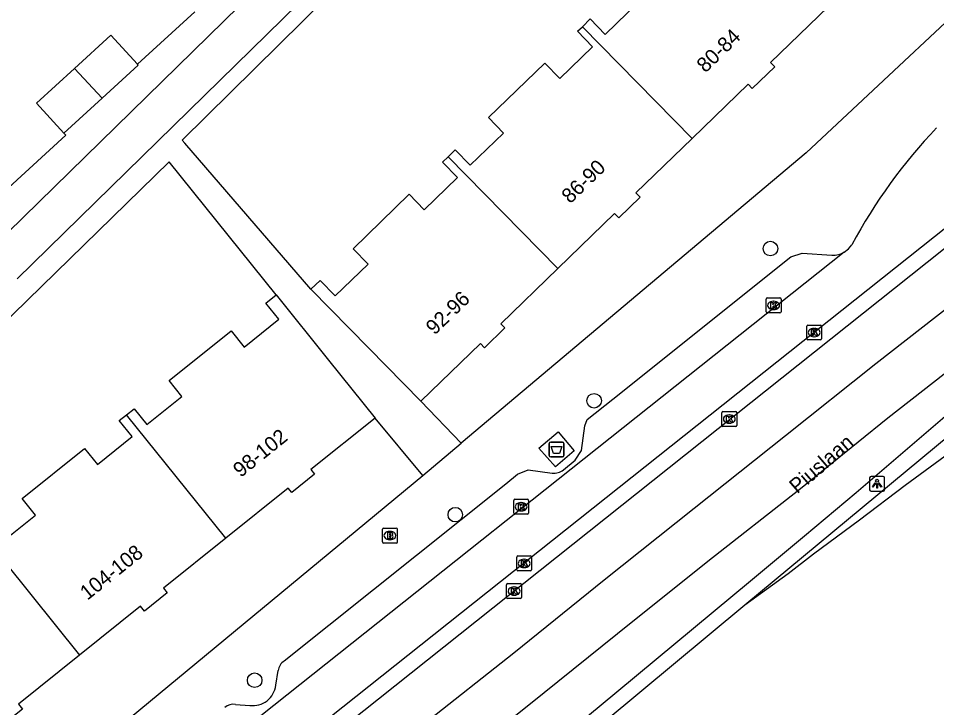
# Model space of a CAD drawing. Extents: x 161882 to 162509, y 381687 to 382379.
# Drawn here: x 162409.8 to 162471.6, y 381766.4 to 381812.8 of the extents above; entities that cross this region are included whole.
import ezdxf

# ---------------------------------------------------------------- set-up
doc = ezdxf.new("R2010")
doc.units = 0
for name, color, linetype in [('IMGEO_Afval_apart_plaats', 7, 'Continuous'), ('IMGEO_Boom', 7, 'Continuous'), ('IMGEO_Brandkraan', 7, 'Continuous'), ('IMGEO_Fietspad_gesloten', 7, 'Continuous'), ('IMGEO_Kolk', 7, 'Continuous'), ('IMGEO_Lichtpunt', 7, 'Continuous'), ('IMGEO_Openbare_ruimte_label', 7, 'Continuous'), ('IMGEO_Pand', 7, 'Continuous'), ('IMGEO_Pand_nummerreeks', 7, 'Continuous'), ('IMGEO_Rijbaan_regionaal_gesloten', 7, 'Continuous'), ('IMGEO_Voetpad_gesloten', 7, 'Continuous'), ('IMGEO_Voetpad_open', 7, 'Continuous')]:
    doc.layers.add(name, color=color, linetype=linetype)

msp = doc.modelspace()

# ---------------------------------------------------------------- linework, layer by layer
at = {"layer": 'IMGEO_Afval_apart_plaats'}
for p, q in [((162445.646, 381784.28), (162446.436, 381784.28)), ((162446.436, 381784.28), (162445.646, 381784.28)), ((162445.546, 381783.38), (162445.546, 381784.18)), ((162445.546, 381784.18), (162445.546, 381783.38)), ((162446.536, 381784.18), (162446.536, 381783.38)), ((162446.536, 381783.38), (162446.536, 381784.18)), ((162446.436, 381783.28), (162445.646, 381783.28)), ((162445.646, 381783.28), (162446.436, 381783.28))]:
    msp.add_line(p, q, dxfattribs=at)
msp.add_lwpolyline([(162445.689, 381783.994), (162446.393, 381783.994), (162446.244, 381783.524), (162445.838, 381783.524), (162445.689, 381783.994)], dxfattribs=at)
for centre, start, end in [((162445.646, 381784.18), 90, 180), ((162445.646, 381784.18), 90, 180), ((162446.436, 381784.18), 0, 90), ((162446.436, 381784.18), 360, 90), ((162445.646, 381783.38), 180, 270), ((162445.646, 381783.38), 180, 270), ((162446.436, 381783.38), 270, 0), ((162446.436, 381783.38), 270, 0)]:
    msp.add_arc(centre, 0.1, start, end, dxfattribs=at)
at = {"layer": 'IMGEO_Boom'}
for centre in [(162460.421, 381797.298), (162448.567, 381787.061), (162439.23, 381779.399), (162425.739, 381768.261)]:
    msp.add_circle(centre, 0.489, dxfattribs=at)
at = {"layer": 'IMGEO_Brandkraan'}
for p, q in [((162434.332, 381777.567), (162434.332, 381778.419)), ((162434.407, 381778.493), (162435.259, 381778.493)), ((162434.82, 381778.273), (162434.845, 381778.273)), ((162435.333, 381778.419), (162435.333, 381777.567)), ((162435.259, 381777.493), (162434.407, 381777.493)), ((162434.843, 381777.713), (162434.818, 381777.713))]:
    msp.add_line(p, q, dxfattribs=at)
for points in [[(162434.332, 381777.567), (162434.332, 381778.419)], [(162434.407, 381778.493), (162435.259, 381778.493)], [(162434.68, 381778.193), (162434.68, 381777.793), (162434.893, 381777.793)], [(162434.911, 381778.193), (162434.68, 381778.193)], [(162434.859, 381778.112), (162434.805, 381778.112), (162434.805, 381778.036)], [(162434.805, 381778.036), (162434.858, 381778.036)], [(162435.333, 381778.419), (162435.333, 381777.567)], [(162435.259, 381777.493), (162434.407, 381777.493)], [(162434.867, 381777.96), (162434.805, 381777.96), (162434.805, 381777.879)], [(162434.805, 381777.879), (162434.867, 381777.879)]]:
    msp.add_lwpolyline(points, dxfattribs=at)
for centre, radius, start, end in [((162434.409, 381778.417), 0.0765, 91.55205, 178.44795), ((162434.409, 381778.417), 0.0765, 91.55205, 178.44795), ((162434.86, 381778.074), 0.0379, 267.82845, 90.93552), ((162434.915, 381778.048), 0.145, 59.4692, 91.53667), ((162434.94, 381778.095), 0.0922, 285.51372, 58.15012), ((162435.257, 381778.417), 0.0765, 1.55205, 88.44795), ((162435.257, 381778.417), 0.0765, 1.55205, 88.44795), ((162434.409, 381777.569), 0.0765, 181.55205, 268.44795), ((162434.409, 381777.569), 0.0765, 181.55205, 268.44795), ((162434.868, 381777.919), 0.0404, 269.87594, 90.50774), ((162434.899, 381778.044), 0.251, 268.66757, 293.53466), ((162434.945, 381777.903), 0.105, 301.31148, 78.98903), ((162435.257, 381777.569), 0.0765, 271.55205, 358.44795), ((162435.257, 381777.569), 0.0765, 271.55205, 358.44795)]:
    msp.add_arc(centre, radius, start, end, dxfattribs=at)
for centre, major_axis, ratio, start_param, end_param in [((162434.819, 381777.993), (-0.387, 0.002), 0.722429, 4.712389, 7.853982), ((162434.844, 381777.993), (-0.39, 0.002), 0.717154, 1.570796, 4.712389)]:
    msp.add_ellipse(centre, major_axis=major_axis, ratio=ratio, start_param=start_param, end_param=end_param, dxfattribs=at)
at = {"layer": 'IMGEO_Fietspad_gesloten'}
for points in [[(162472.336, 381798.789), (162413.971, 381752.357), (162396.799, 381738.137)], [(162465.384, 381797.056), (162465.667, 381797.275), (162465.9, 381797.559)], [(162465.384, 381797.056), (162418.283, 381759.605), (162412.351, 381754.828), (162394.327, 381740.001), (162393.522, 381739.663)]]:
    msp.add_lwpolyline(points, dxfattribs=at)
msp.add_arc((162497.514, 381780.636), 35.859, 136.27808, 151.83984, dxfattribs=at)
at = {"layer": 'IMGEO_Kolk'}
for p, q in [((162460.133, 381793.05), (162460.133, 381793.902)), ((162460.208, 381793.976), (162461.06, 381793.976)), ((162460.621, 381793.756), (162460.646, 381793.756)), ((162461.134, 381793.902), (162461.134, 381793.05)), ((162461.06, 381792.976), (162460.208, 381792.976)), ((162460.644, 381793.196), (162460.619, 381793.196)), ((162462.862, 381791.224), (162462.862, 381792.076)), ((162462.937, 381792.15), (162463.789, 381792.15)), ((162463.35, 381791.93), (162463.375, 381791.93)), ((162463.863, 381792.076), (162463.863, 381791.224)), ((162463.789, 381791.15), (162462.937, 381791.15)), ((162463.373, 381791.37), (162463.348, 381791.37)), ((162457.158, 381785.406), (162457.158, 381786.258)), ((162457.233, 381786.332), (162458.085, 381786.332)), ((162457.646, 381786.112), (162457.671, 381786.112)), ((162458.159, 381786.258), (162458.159, 381785.406)), ((162457.669, 381785.552), (162457.644, 381785.552)), ((162458.085, 381785.332), (162457.233, 381785.332)), ((162443.157, 381779.505), (162443.157, 381780.357)), ((162443.232, 381780.431), (162444.084, 381780.431)), ((162443.645, 381780.211), (162443.67, 381780.211)), ((162444.158, 381780.357), (162444.158, 381779.505)), ((162444.084, 381779.431), (162443.232, 381779.431)), ((162443.668, 381779.651), (162443.643, 381779.651)), ((162443.362, 381775.693), (162443.362, 381776.545)), ((162443.437, 381776.619), (162444.289, 381776.619)), ((162443.85, 381776.399), (162443.875, 381776.399)), ((162444.363, 381776.545), (162444.363, 381775.693)), ((162444.289, 381775.619), (162443.437, 381775.619)), ((162443.873, 381775.839), (162443.848, 381775.839)), ((162442.685, 381773.835), (162442.685, 381774.687)), ((162442.76, 381774.761), (162443.612, 381774.761)), ((162443.173, 381774.541), (162443.198, 381774.541)), ((162443.686, 381774.687), (162443.686, 381773.835)), ((162443.612, 381773.761), (162442.76, 381773.761)), ((162443.196, 381773.981), (162443.171, 381773.981))]:
    msp.add_line(p, q, dxfattribs=at)
for points in [[(162460.133, 381793.05), (162460.133, 381793.902)], [(162460.208, 381793.976), (162461.06, 381793.976)], [(162460.454, 381793.676), (162460.577, 381793.676), (162460.577, 381793.525), (162460.707, 381793.676), (162460.871, 381793.676), (162460.725, 381793.525), (162460.878, 381793.276), (162460.726, 381793.276), (162460.641, 381793.44), (162460.577, 381793.373), (162460.577, 381793.276), (162460.454, 381793.276), (162460.454, 381793.676)], [(162461.134, 381793.902), (162461.134, 381793.05)], [(162461.06, 381792.976), (162460.208, 381792.976)], [(162462.862, 381791.224), (162462.862, 381792.076)], [(162462.937, 381792.15), (162463.789, 381792.15)], [(162463.183, 381791.85), (162463.306, 381791.85), (162463.306, 381791.699), (162463.436, 381791.85), (162463.6, 381791.85), (162463.454, 381791.699), (162463.607, 381791.45), (162463.455, 381791.45), (162463.37, 381791.614), (162463.306, 381791.547), (162463.306, 381791.45), (162463.183, 381791.45), (162463.183, 381791.85)], [(162463.863, 381792.076), (162463.863, 381791.224)], [(162463.789, 381791.15), (162462.937, 381791.15)], [(162457.158, 381785.406), (162457.158, 381786.258)], [(162457.233, 381786.332), (162458.085, 381786.332)], [(162458.159, 381786.258), (162458.159, 381785.406)], [(162457.479, 381786.032), (162457.602, 381786.032), (162457.602, 381785.881), (162457.732, 381786.032), (162457.896, 381786.032), (162457.75, 381785.881), (162457.903, 381785.632), (162457.751, 381785.632), (162457.666, 381785.796), (162457.602, 381785.729), (162457.602, 381785.632), (162457.479, 381785.632), (162457.479, 381786.032)], [(162458.085, 381785.332), (162457.233, 381785.332)], [(162443.157, 381779.505), (162443.157, 381780.357)], [(162443.232, 381780.431), (162444.084, 381780.431)], [(162443.478, 381780.131), (162443.601, 381780.131), (162443.601, 381779.98), (162443.731, 381780.131), (162443.895, 381780.131), (162443.749, 381779.98), (162443.902, 381779.731), (162443.75, 381779.731), (162443.665, 381779.895), (162443.601, 381779.828), (162443.601, 381779.731), (162443.478, 381779.731), (162443.478, 381780.131)], [(162444.158, 381780.357), (162444.158, 381779.505)], [(162444.084, 381779.431), (162443.232, 381779.431)], [(162443.362, 381775.693), (162443.362, 381776.545)], [(162443.437, 381776.619), (162444.289, 381776.619)], [(162443.683, 381776.319), (162443.806, 381776.319), (162443.806, 381776.168), (162443.936, 381776.319), (162444.1, 381776.319), (162443.954, 381776.168), (162444.107, 381775.919), (162443.955, 381775.919), (162443.87, 381776.083), (162443.806, 381776.016), (162443.806, 381775.919), (162443.683, 381775.919), (162443.683, 381776.319)], [(162444.363, 381776.545), (162444.363, 381775.693)], [(162444.289, 381775.619), (162443.437, 381775.619)], [(162442.685, 381773.835), (162442.685, 381774.687)], [(162442.76, 381774.761), (162443.612, 381774.761)], [(162443.006, 381774.461), (162443.129, 381774.461), (162443.129, 381774.31), (162443.259, 381774.461), (162443.423, 381774.461), (162443.277, 381774.31), (162443.43, 381774.061), (162443.278, 381774.061), (162443.193, 381774.225), (162443.129, 381774.158), (162443.129, 381774.061), (162443.006, 381774.061), (162443.006, 381774.461)], [(162443.686, 381774.687), (162443.686, 381773.835)], [(162443.612, 381773.761), (162442.76, 381773.761)]]:
    msp.add_lwpolyline(points, dxfattribs=at)
for centre, start, end in [((162460.21, 381793.9), 91.55205, 178.44795), ((162460.21, 381793.9), 91.55205, 178.44795), ((162461.058, 381793.9), 1.55205, 88.44795), ((162461.058, 381793.9), 1.55205, 88.44795), ((162460.21, 381793.052), 181.55205, 268.44795), ((162460.21, 381793.052), 181.55205, 268.44795), ((162461.058, 381793.052), 271.55205, 358.44795), ((162461.058, 381793.052), 271.55205, 358.44795), ((162462.939, 381792.074), 91.55205, 178.44795), ((162462.939, 381792.074), 91.55205, 178.44795), ((162463.787, 381792.074), 1.55205, 88.44795), ((162463.787, 381792.074), 1.55205, 88.44795), ((162462.939, 381791.226), 181.55205, 268.44795), ((162462.939, 381791.226), 181.55205, 268.44795), ((162463.787, 381791.226), 271.55205, 358.44795), ((162463.787, 381791.226), 271.55205, 358.44795), ((162457.235, 381786.256), 91.55205, 178.44795), ((162457.235, 381786.256), 91.55205, 178.44795), ((162458.083, 381786.256), 1.55205, 88.44795), ((162458.083, 381786.256), 1.55205, 88.44795), ((162457.235, 381785.408), 181.55205, 268.44795), ((162457.235, 381785.408), 181.55205, 268.44795), ((162458.083, 381785.408), 271.55205, 358.44795), ((162458.083, 381785.408), 271.55205, 358.44795), ((162443.234, 381780.355), 91.55205, 178.44795), ((162443.234, 381780.355), 91.55205, 178.44795), ((162444.082, 381780.355), 1.55205, 88.44795), ((162444.082, 381780.355), 1.55205, 88.44795), ((162443.234, 381779.507), 181.55205, 268.44795), ((162443.234, 381779.507), 181.55205, 268.44795), ((162444.082, 381779.507), 271.55205, 358.44795), ((162444.082, 381779.507), 271.55205, 358.44795), ((162443.439, 381776.543), 91.55205, 178.44795), ((162443.439, 381776.543), 91.55205, 178.44795), ((162444.287, 381776.543), 1.55205, 88.44795), ((162444.287, 381776.543), 1.55205, 88.44795), ((162443.439, 381775.695), 181.55205, 268.44795), ((162443.439, 381775.695), 181.55205, 268.44795), ((162444.287, 381775.695), 271.55205, 358.44795), ((162444.287, 381775.695), 271.55205, 358.44795), ((162442.762, 381774.685), 91.55205, 178.44795), ((162442.762, 381774.685), 91.55205, 178.44795), ((162443.61, 381774.685), 1.55205, 88.44795), ((162443.61, 381774.685), 1.55205, 88.44795), ((162442.762, 381773.837), 181.55205, 268.44795), ((162442.762, 381773.837), 181.55205, 268.44795), ((162443.61, 381773.837), 271.55205, 358.44795), ((162443.61, 381773.837), 271.55205, 358.44795)]:
    msp.add_arc(centre, 0.0765, start, end, dxfattribs=at)
for centre, major_axis, ratio, start_param, end_param in [((162460.62, 381793.476), (-0.387, 0.002), 0.722429, 4.712389, 7.853982), ((162460.645, 381793.476), (-0.39, 0.002), 0.717154, 1.570796, 4.712389), ((162463.349, 381791.65), (-0.387, 0.002), 0.722429, 4.712389, 7.853982), ((162463.374, 381791.65), (-0.39, 0.002), 0.717154, 1.570796, 4.712389), ((162457.645, 381785.832), (-0.387, 0.002), 0.722429, 4.712389, 7.853982), ((162457.67, 381785.832), (-0.39, 0.002), 0.717154, 1.570796, 4.712389), ((162443.644, 381779.931), (-0.387, 0.002), 0.722429, 4.712389, 7.853982), ((162443.669, 381779.931), (-0.39, 0.002), 0.717154, 1.570796, 4.712389), ((162443.849, 381776.119), (-0.387, 0.002), 0.722429, 4.712389, 7.853982), ((162443.874, 381776.119), (-0.39, 0.002), 0.717154, 1.570796, 4.712389), ((162443.172, 381774.261), (-0.387, 0.002), 0.722429, 4.712389, 7.853982), ((162443.197, 381774.261), (-0.39, 0.002), 0.717154, 1.570796, 4.712389)]:
    msp.add_ellipse(centre, major_axis=major_axis, ratio=ratio, start_param=start_param, end_param=end_param, dxfattribs=at)
at = {"layer": 'IMGEO_Lichtpunt'}
for p, q in [((162467.093, 381781.879), (162467.093, 381781.072)), ((162467.093, 381781.879), (162467.093, 381781.072)), ((162467.995, 381781.974), (162467.187, 381781.974)), ((162467.995, 381781.974), (162467.187, 381781.974)), ((162468.089, 381781.072), (162468.089, 381781.879)), ((162468.089, 381781.072), (162468.089, 381781.879)), ((162467.187, 381780.978), (162467.995, 381780.978)), ((162467.187, 381780.978), (162467.995, 381780.978))]:
    msp.add_line(p, q, dxfattribs=at)
for points in [[(162467.467, 381781.543), (162467.506, 381781.515), (162467.318, 381781.253), (162467.28, 381781.28), (162467.467, 381781.543)], [(162467.569, 381781.495), (162467.616, 381781.495), (162467.616, 381781.173), (162467.569, 381781.173), (162467.569, 381781.495)], [(162467.679, 381781.515), (162467.717, 381781.542), (162467.904, 381781.28), (162467.865, 381781.252), (162467.679, 381781.515)]]:
    msp.add_lwpolyline(points, dxfattribs=at)
msp.add_circle((162467.592, 381781.677), 0.0994, dxfattribs=at)
for centre, start, end in [((162467.187, 381781.879), 90, 180), ((162467.187, 381781.879), 90, 180), ((162467.995, 381781.879), 0, 90), ((162467.995, 381781.879), 0, 90), ((162467.187, 381781.072), 180, 270), ((162467.187, 381781.072), 180, 270), ((162467.995, 381781.072), 270, 0), ((162467.995, 381781.072), 270, 360)]:
    msp.add_arc(centre, 0.0946, start, end, dxfattribs=at)
at = {"layer": 'IMGEO_Pand'}
for points in [[(162456.915, 381821.079), (162456.549, 381820.724), (162457.558, 381819.683), (162455.331, 381817.526), (162454.322, 381818.567), (162450.544, 381814.907), (162451.553, 381813.866), (162449.319, 381811.703), (162448.31, 381812.744), (162447.776, 381812.227)], [(162408.087, 381797.371), (162426.783, 381815.673)], [(162428.663, 381813.756), (162409.777, 381795.269)], [(162455.154, 381804.701), (162458.924, 381808.352), (162459.203, 381808.065), (162460.711, 381809.526), (162460.432, 381809.813), (162464.294, 381813.553)], [(162438.742, 381803.476), (162439.224, 381803.942), (162440.233, 381802.901), (162442.474, 381805.072), (162441.465, 381806.113), (162445.243, 381809.773), (162446.252, 381808.732), (162448.464, 381810.875), (162447.455, 381811.916), (162447.776, 381812.227)], [(162447.776, 381812.227), (162455.154, 381804.701)], [(162413.626, 381809.42), (162416.068, 381811.651), (162417.855, 381809.694)], [(162415.495, 381807.419), (162417.915, 381809.629), (162417.855, 381809.694)], [(162412.909, 381805.058), (162411.063, 381807.08), (162413.626, 381809.42)], [(162413.626, 381809.42), (162415.495, 381807.419)], [(162415.495, 381807.419), (162412.909, 381805.058)], [(162455.154, 381804.701), (162451.381, 381801.048), (162451.66, 381800.761), (162450.223, 381799.369), (162449.944, 381799.656), (162446.119, 381795.952)], [(162438.742, 381803.476), (162438.369, 381803.114), (162439.378, 381802.073), (162437.144, 381799.91), (162436.135, 381800.951), (162432.357, 381797.291), (162433.366, 381796.25), (162431.161, 381794.114), (162430.152, 381795.155), (162429.518, 381794.561)], [(162446.119, 381795.952), (162438.742, 381803.476)], [(162436.906, 381787.029), (162440.915, 381790.911), (162441.194, 381790.624), (162442.573, 381791.96), (162442.294, 381792.247), (162446.119, 381795.952)], [(162417.13, 381786.119), (162417.637, 381786.526), (162418.49, 381785.464), (162420.842, 381787.353), (162419.989, 381788.416), (162424.149, 381791.757), (162425.029, 381790.66), (162427.372, 381792.541), (162426.496, 381793.632), (162427.183, 381794.183)], [(162427.183, 381794.183), (162430.705, 381789.797), (162433.836, 381785.898)], [(162436.906, 381787.029), (162433.414, 381790.589), (162429.518, 381794.561)], [(162407.314, 381778.223), (162407.768, 381778.588), (162408.653, 381777.486), (162411.003, 381779.373), (162410.105, 381780.491), (162414.302, 381783.861), (162415.174, 381782.775), (162417.505, 381784.647), (162416.639, 381785.725), (162417.13, 381786.119)], [(162423.796, 381777.824), (162417.13, 381786.119)], [(162433.836, 381785.898), (162429.524, 381782.435), (162429.773, 381782.125), (162428.235, 381780.891), (162427.992, 381781.193), (162423.796, 381777.824)], [(162407.314, 381778.223), (162413.962, 381769.95)], [(162423.796, 381777.824), (162419.601, 381774.456), (162419.852, 381774.144), (162418.326, 381772.919), (162418.065, 381773.244), (162413.962, 381769.95)], [(162413.962, 381769.95), (162409.859, 381766.656), (162410.127, 381766.323), (162408.569, 381765.072), (162408.327, 381765.372), (162404.147, 381762.016)]]:
    msp.add_lwpolyline(points, dxfattribs=at)
at = {"layer": 'IMGEO_Rijbaan_regionaal_gesloten'}
for points in [[(162354.918, 381703.865), (162355.932, 381704.593), (162374.687, 381717.125), (162383.304, 381723.196), (162388.283, 381726.848), (162394.39, 381731.453), (162400.577, 381736.34), (162406.68, 381741.16), (162412.783, 381745.979), (162418.885, 381750.799), (162424.953, 381755.663), (162430.995, 381760.424), (162437.093, 381765.307), (162443.174, 381770.102), (162449.253, 381775.014), (162455.293, 381779.828), (162461.432, 381784.719), (162467.508, 381789.56), (162473.626, 381794.349), (162479.733, 381799.057), (162485.928, 381803.772), (162492.011, 381808.462), (162495.338, 381811.162)], [(162497.319, 381808.357), (162492.901, 381805.153), (162480.582, 381795.502), (162474.449, 381790.697), (162468.315, 381785.892), (162462.329, 381781.05), (162456.203, 381776.256), (162450.144, 381771.379), (162444.176, 381766.576), (162438.061, 381761.719), (162431.945, 381756.862), (162428.87, 381754.42), (162422.805, 381749.603), (162416.695, 381744.75), (162410.545, 381739.948), (162404.375, 381735.051)], [(162497.319, 381808.357), (162484.786, 381797.114), (162471.985, 381785.848), (162466.19, 381780.862), (162462.706, 381777.955), (162459.087, 381774.927), (162448.913, 381766.462), (162439.29, 381758.51), (162435.039, 381754.997), (162428.916, 381750), (162421.805, 381744.196)], [(162502.913, 381804.071), (162494.7, 381798.828), (162493.976, 381798.359), (162490.981, 381796.418), (162487.82, 381794.369), (162484.689, 381792.273), (162481.612, 381790.099), (162478.605, 381787.975), (162475.539, 381785.809), (162472.516, 381783.584), (162469.493, 381781.359), (162466.423, 381779.021), (162463.311, 381776.74), (162461.613, 381775.429), (162458.703, 381773.301)], [(162397.154, 381737.782), (162428.678, 381762.735), (162473.156, 381798.141)], [(162480.401, 381791.319), (162458.703, 381773.301)], [(162458.703, 381773.301), (162449.246, 381765.447), (162448.728, 381765.02), (162430.504, 381750), (162395.982, 381721.548)]]:
    msp.add_lwpolyline(points, dxfattribs=at)
at = {"layer": 'IMGEO_Voetpad_gesloten'}
msp.add_lwpolyline([(162446.154, 381784.966), (162447.229, 381783.689), (162445.965, 381782.625), (162444.852, 381783.87), (162446.154, 381784.966)], dxfattribs=at)
at = {"layer": 'IMGEO_Voetpad_open'}
for points in [[(162429.518, 381794.561), (162421.052, 381804.384), (162420.873, 381804.592), (162456.614, 381839.875)], [(162478.012, 381817.966), (162477.732, 381817.717), (162462.828, 381803.734), (162439.634, 381784.212)], [(162417.855, 381809.694), (162421.709, 381813.214)], [(162409.204, 381801.418), (162413.037, 381804.918), (162412.909, 381805.058)], [(162427.183, 381794.183), (162419.997, 381803.132), (162406.611, 381790.087), (162388.399, 381772.337), (162385.299, 381769.316), (162384.304, 381770.332)], [(162446.507, 381782.417), (162447.288, 381783.074), (162447.713, 381783.712), (162447.942, 381785.382), (162448.089, 381785.805), (162449.816, 381787.175), (162461.805, 381796.747), (162462.558, 381796.999), (162464.562, 381796.862)], [(162439.634, 381784.212), (162436.906, 381787.029)], [(162437.038, 381782.026), (162433.836, 381785.898)], [(162437.038, 381782.026), (162439.634, 381784.212)], [(162427.727, 381769.559), (162442.627, 381781.463), (162443.425, 381782.118), (162444.138, 381782.406), (162445.749, 381782.196)], [(162342.256, 381716.825), (162343.866, 381713.286), (162356.915, 381719.329), (162365.839, 381723.151), (162398.308, 381750), (162437.038, 381782.026)], [(162427.158, 381767.928), (162427.313, 381768.906)], [(162424.449, 381766.638), (162425.423, 381766.569)]]:
    msp.add_lwpolyline(points, dxfattribs=at)
for centre, radius, start, end in [((162464.688, 381798.167), 1.311, 264.49334, 302.06539), ((162445.862, 381783.22), 1.03, 263.72274, 308.78605), ((162428.273, 381768.755), 0.972, 124.1889, 171.06196), ((162425.622, 381768.102), 1.546, 262.61397, 353.52818), ((162424.336, 381765.761), 0.884, 82.645, 132.01677)]:
    msp.add_arc(centre, radius, start, end, dxfattribs=at)

# ---------------------------------------------------------------- texts
at = {"layer": 'IMGEO_Openbare_ruimte_label'}
msp.add_text('Piuslaan', height=1, rotation=40.70074, dxfattribs=at).set_placement((162462.223, 381780.769))
at = {"layer": 'IMGEO_Pand_nummerreeks'}
for s, rotation, p in [('80-84', 44.08299, (162456.05, 381809.077)), ('86-90', 44.08177, (162446.961, 381800.275)), ('92-96', 44.0823, (162437.835, 381791.437)), ('98-102', 38.80532, (162424.796, 381781.861)), ('104-108', 38.68431, (162414.495, 381773.606))]:
    msp.add_text(s, height=1, rotation=rotation, dxfattribs=at).set_placement(p)

doc.saveas('drawing.dxf')
